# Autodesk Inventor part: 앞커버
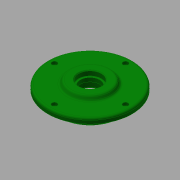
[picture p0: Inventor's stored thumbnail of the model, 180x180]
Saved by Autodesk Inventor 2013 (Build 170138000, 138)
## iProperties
Created: 2016-11
Part Number: 앞커버
Material: 일반
Document SubType Name: Modeling
Designer: mduedu
Density: 2.71 g/cm^3
Mass: 511.35 g
Surface Area: 365.029 cm^2
Volume: 188.69 cm^3
Author: mduedu
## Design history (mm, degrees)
sketch "스케치1"
  geometry: L1 (28.5, -17.5)-(28.5, -30); L2 (28.5, -30)-(22.5, -33.464); L3 (22.5, -33.464)-(22.5, -65); L4 (22.5, -65)-(14.5, -65); L5 (14.5, -65)-(14.5, -47.5); L6 (14.5, -47.5)-(0, -47.5); L7 (0, -47.5)-(0, -23.5); L8 (0, 0)-(28.5, 0); L9 (14.5, -23.5)-(14.5, -15); L10 (14.5, -15)-(20.5, -15); L11 (20.5, -15)-(20.5, -17.5); L12 (0, -23.5)-(14.5, -23.5); L13 (20.5, -17.5)-(28.5, -17.5)
  constraints: 26 end point, 8 parallel, 3 perpendicular, 2 horizontal, 2 vertical alignment, 1 collinear
  dimensions: "d0" = 14.5 distance of L5.end L6.end; "d2" = 8 distance of L3.end L4.end; "d3" = 6 distance between parallel lines of L1 L3; "d4" = 120 deg angle of L3 L2; "d5" = 8 distance of L11.end L1.start; "d6" = 60 diameter of L1.end L8; "d7" = 30 diameter of L10 L8; "d8" = 47 diameter of L12 L8; "d9" = 35 diameter of L13 L8; "d10" = 95 diameter of L6 L8; "d11" = 130 diameter of L4 L8
revolve "회전1" sketch "스케치1" stored, may be unused: angle "d12" = 90 deg
fillet "모깎기1" dims "d13" = 0.5
fillet "모깎기2" dims "d14" = 3
chamfer "모따기1" distance "d15" = 1; stored, may be unused: second distance "d16" = 2, angle "d17" = 45 deg
fillet "모깎기3" dims "d18" = 0.3
sketch "스케치2" dims "d19" = 110
  geometry: 6 further points
  constraints: 2 vertical alignment, 1 coincident, 7 other
  dimensions: "d22" = 360 deg dimension on point (0, 0) point (0, 55) (derived)
sketch "스케치3"
  geometry: 4 further points
  constraints: 4 other
hole "구멍1" sketch "스케치3" at (0, 55), (-55, 0), (55, 0), (0, -55) diameter "d24" = 4.5; stored, may be unused: countersink angle "d28" = 90 deg, drill point angle "d30" = 0 deg; dims "d25" = 6, "d26" = 8, "d27" = 4.6, "d29" = 8
node "솔리드1"
